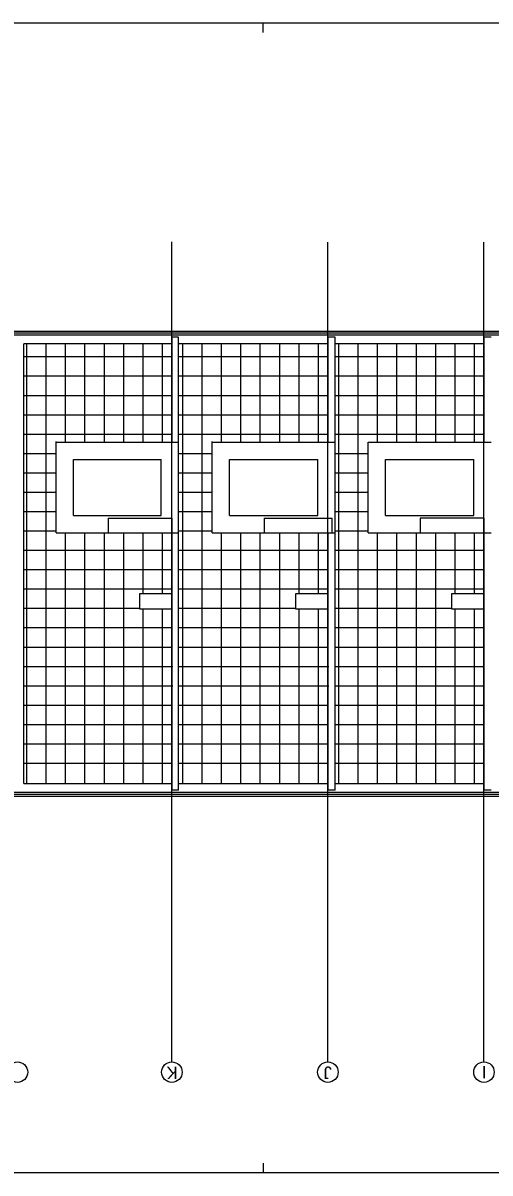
# Model space of a CAD drawing. Extents: x 1278 to 1356, y -443 to -224.
# Drawn here: x 1299.56 to 1311.63, y -253.66 to -223.96 of the extents above; entities that cross this region are included whole.
import ezdxf

# ---------------------------------------------------------------- set-up
doc = ezdxf.new("R2010")
doc.units = 0
for name, color, linetype in [('estrutura-eixos', 7, 'Continuous'), ('Level 2', 7, 'Continuous'), ('Level 21', 7, 'Continuous'), ('Level 60', 7, 'Continuous'), ('Level 62', 7, 'Continuous'), ('Level 70', 7, 'Continuous')]:
    doc.layers.add(name, color=color, linetype=linetype)

msp = doc.modelspace()

# ---------------------------------------------------------------- linework, layer by layer
at = {"layer": 'estrutura-eixos'}
for p, q in [((1303.409, -250.792), (1303.409, -229.609)), ((1307.439, -250.792), (1307.439, -229.62)), ((1311.469, -250.792), (1311.469, -229.62))]:
    msp.add_line(p, q, dxfattribs=at)
at = {"layer": 'Level 2'}
for p, q in [((1303.409, -232.244), (1299.582, -232.244)), ((1307.439, -232.244), (1303.578, -232.244)), ((1311.469, -232.244), (1307.628, -232.244)), ((1299.582, -243.604), (1303.409, -243.604)), ((1303.578, -243.604), (1307.439, -243.604)), ((1307.628, -243.604), (1311.469, -243.604))]:
    msp.add_line(p, q, dxfattribs=at)
at = {"layer": 'Level 21'}
for p, q in [((1299.664, -243.604), (1299.664, -232.244)), ((1300.164, -243.604), (1300.164, -232.244)), ((1300.664, -234.765), (1300.664, -232.244)), ((1301.164, -234.765), (1301.164, -232.244)), ((1301.664, -234.765), (1301.664, -232.244)), ((1302.164, -234.765), (1302.164, -232.244)), ((1302.664, -234.765), (1302.664, -232.244)), ((1303.164, -234.765), (1303.164, -232.244)), ((1303.693, -243.604), (1303.693, -232.244)), ((1304.193, -243.604), (1304.193, -232.244)), ((1304.693, -234.765), (1304.693, -232.244)), ((1305.193, -234.765), (1305.193, -232.244)), ((1305.693, -234.765), (1305.693, -232.244)), ((1306.193, -234.765), (1306.193, -232.244)), ((1306.693, -234.765), (1306.693, -232.244)), ((1307.193, -234.765), (1307.193, -232.244)), ((1307.723, -243.604), (1307.723, -232.244)), ((1308.223, -243.604), (1308.223, -232.244)), ((1308.723, -234.785), (1308.723, -232.244)), ((1309.223, -234.785), (1309.223, -232.244)), ((1309.723, -234.785), (1309.723, -232.244)), ((1310.223, -234.785), (1310.223, -232.244)), ((1310.723, -234.785), (1310.723, -232.244)), ((1311.223, -234.785), (1311.223, -232.244)), ((1303.409, -232.584), (1299.582, -232.584)), ((1307.439, -232.584), (1303.578, -232.584)), ((1311.469, -232.584), (1307.628, -232.584)), ((1303.409, -233.084), (1299.582, -233.084)), ((1307.439, -233.084), (1303.578, -233.084)), ((1311.469, -233.084), (1307.628, -233.084)), ((1303.409, -233.584), (1299.582, -233.584)), ((1307.439, -233.584), (1303.578, -233.584)), ((1311.469, -233.584), (1307.628, -233.584)), ((1303.409, -234.084), (1299.582, -234.084)), ((1307.439, -234.084), (1303.578, -234.084)), ((1311.469, -234.084), (1307.628, -234.084)), ((1303.409, -234.584), (1299.582, -234.584)), ((1307.439, -234.584), (1303.578, -234.584)), ((1311.469, -234.584), (1307.628, -234.584)), ((1300.419, -235.084), (1299.582, -235.084)), ((1304.449, -235.084), (1303.578, -235.084)), ((1308.479, -235.084), (1307.628, -235.084)), ((1300.419, -235.584), (1299.582, -235.584)), ((1304.449, -235.584), (1303.578, -235.584)), ((1308.479, -235.584), (1307.628, -235.584)), ((1300.419, -236.084), (1299.582, -236.084)), ((1304.449, -236.084), (1303.578, -236.084)), ((1308.479, -236.084), (1307.628, -236.084)), ((1300.419, -236.584), (1299.582, -236.584)), ((1304.449, -236.584), (1303.578, -236.584)), ((1308.479, -236.584), (1307.628, -236.584)), ((1300.419, -237.084), (1299.582, -237.084)), ((1300.664, -243.604), (1300.664, -237.126)), ((1301.164, -243.604), (1301.164, -237.126)), ((1301.664, -243.604), (1301.664, -237.126)), ((1302.164, -243.604), (1302.164, -237.126)), ((1302.664, -238.706), (1302.664, -237.126)), ((1303.164, -238.706), (1303.164, -237.126)), ((1304.449, -237.084), (1303.578, -237.084)), ((1304.693, -243.604), (1304.693, -237.127)), ((1305.193, -243.604), (1305.193, -237.127)), ((1305.693, -243.604), (1305.693, -237.127)), ((1306.193, -243.604), (1306.193, -237.127)), ((1306.693, -238.706), (1306.693, -237.127)), ((1307.193, -238.706), (1307.193, -237.127)), ((1308.479, -237.084), (1307.628, -237.084)), ((1308.723, -243.604), (1308.723, -237.126)), ((1309.223, -243.604), (1309.223, -237.126)), ((1309.723, -243.604), (1309.723, -237.126)), ((1310.223, -243.604), (1310.223, -237.126)), ((1310.723, -238.706), (1310.723, -237.126)), ((1311.223, -238.706), (1311.223, -237.126)), ((1303.409, -237.584), (1299.582, -237.584)), ((1307.439, -237.584), (1303.578, -237.584)), ((1311.469, -237.584), (1307.628, -237.584)), ((1303.409, -238.084), (1299.582, -238.084)), ((1307.439, -238.084), (1303.578, -238.084)), ((1311.469, -238.084), (1307.628, -238.084)), ((1303.409, -238.584), (1299.582, -238.584)), ((1307.439, -238.584), (1303.578, -238.584)), ((1311.469, -238.584), (1307.628, -238.584)), ((1302.57, -239.084), (1299.582, -239.084)), ((1306.599, -239.084), (1303.578, -239.084)), ((1310.629, -239.084), (1307.628, -239.084)), ((1302.664, -243.604), (1302.664, -239.086)), ((1303.164, -243.604), (1303.164, -239.086)), ((1306.693, -243.604), (1306.693, -239.086)), ((1307.193, -243.604), (1307.193, -239.086)), ((1310.723, -243.604), (1310.723, -239.086)), ((1311.223, -243.604), (1311.223, -239.086)), ((1303.409, -239.584), (1299.582, -239.584)), ((1307.439, -239.584), (1303.578, -239.584)), ((1311.469, -239.584), (1307.628, -239.584)), ((1303.409, -240.084), (1299.582, -240.084)), ((1307.439, -240.084), (1303.578, -240.084)), ((1311.469, -240.084), (1307.628, -240.084)), ((1303.429, -240.584), (1299.582, -240.584)), ((1307.459, -240.584), (1303.578, -240.584)), ((1311.469, -240.584), (1307.628, -240.584)), ((1303.429, -241.084), (1299.582, -241.084)), ((1307.459, -241.084), (1303.578, -241.084)), ((1311.469, -241.084), (1307.628, -241.084)), ((1303.409, -241.584), (1299.582, -241.584)), ((1307.439, -241.584), (1303.578, -241.584)), ((1311.469, -241.584), (1307.628, -241.584)), ((1303.409, -242.084), (1299.582, -242.084)), ((1307.439, -242.084), (1303.578, -242.084)), ((1311.469, -242.084), (1307.628, -242.084)), ((1303.409, -242.584), (1299.582, -242.584)), ((1307.439, -242.584), (1303.578, -242.584)), ((1311.469, -242.584), (1307.628, -242.584)), ((1303.409, -243.084), (1299.582, -243.084)), ((1307.439, -243.084), (1303.578, -243.084)), ((1311.469, -243.084), (1307.628, -243.084))]:
    msp.add_line(p, q, dxfattribs=at)
at = {"layer": 'Level 60'}
for centre in [(1299.419, -251.055), (1303.409, -251.055), (1307.439, -251.055), (1311.469, -251.055)]:
    msp.add_circle(centre, 0.265, dxfattribs=at)
at = {"layer": 'Level 62'}
for p, q in [((1305.766, -224.209), (1305.766, -223.959)), ((1305.766, -253.409), (1305.766, -253.659))]:
    msp.add_line(p, q, dxfattribs=at)
msp.add_lwpolyline([(1355.966, -223.959), (1355.966, -253.659), (1278.016, -253.659), (1278.016, -223.959)], close=True, dxfattribs=at)
at = {"layer": 'Level 70'}
for p, q in [((1305.766, -224.209), (1305.766, -223.959)), ((1311.543, -231.924), (1299.193, -231.924)), ((1311.593, -231.924), (1311.543, -231.924)), ((1315.493, -231.924), (1311.593, -231.924)), ((1311.593, -231.974), (1299.193, -231.974)), ((1311.593, -232.024), (1299.193, -232.024)), ((1299.582, -243.604), (1299.582, -232.244)), ((1303.578, -232.074), (1303.409, -232.074)), ((1303.409, -232.074), (1303.409, -234.765)), ((1303.578, -243.774), (1303.578, -232.074)), ((1307.628, -232.074), (1307.439, -232.074)), ((1307.439, -232.074), (1307.439, -234.765)), ((1307.628, -243.774), (1307.628, -232.074)), ((1311.469, -232.074), (1311.469, -234.785)), ((1311.658, -232.074), (1311.469, -232.074)), ((1315.643, -231.974), (1311.593, -231.974)), ((1315.643, -232.024), (1311.593, -232.024)), ((1300.419, -237.126), (1300.419, -234.765)), ((1300.419, -234.785), (1303.578, -234.785)), ((1304.449, -237.127), (1304.449, -234.765)), ((1304.449, -234.785), (1307.628, -234.785)), ((1308.479, -234.785), (1311.658, -234.785)), ((1308.479, -237.126), (1308.479, -234.785)), ((1300.869, -236.676), (1300.869, -235.235)), ((1300.869, -235.235), (1303.128, -235.235)), ((1303.128, -236.676), (1303.128, -235.235)), ((1304.899, -236.677), (1304.899, -235.235)), ((1304.899, -235.235), (1307.178, -235.235)), ((1307.178, -236.677), (1307.178, -235.235)), ((1308.929, -236.676), (1308.929, -235.235)), ((1308.929, -235.235), (1311.208, -235.235)), ((1311.208, -236.676), (1311.208, -235.235)), ((1300.869, -236.676), (1303.128, -236.676)), ((1304.899, -236.677), (1307.178, -236.677)), ((1308.929, -236.676), (1311.208, -236.676)), ((1301.763, -236.745), (1303.42, -236.745)), ((1301.763, -236.745), (1301.763, -237.126)), ((1303.42, -237.126), (1303.42, -236.745)), ((1305.793, -236.745), (1307.549, -236.745)), ((1305.793, -236.745), (1305.793, -237.127)), ((1307.549, -237.127), (1307.549, -236.745)), ((1309.823, -236.745), (1309.823, -237.126)), ((1311.478, -236.745), (1309.823, -236.745)), ((1311.478, -237.126), (1311.478, -236.745)), ((1300.419, -237.126), (1303.578, -237.126)), ((1303.409, -237.126), (1303.409, -243.774)), ((1304.449, -237.127), (1307.628, -237.127)), ((1307.439, -237.127), (1307.439, -243.774)), ((1308.479, -237.126), (1311.658, -237.126)), ((1311.469, -237.126), (1311.469, -243.774)), ((1299.193, -243.824), (1318.344, -243.824)), ((1303.578, -243.774), (1303.409, -243.774)), ((1307.628, -243.774), (1307.439, -243.774)), ((1311.658, -243.774), (1311.469, -243.774)), ((1299.193, -243.874), (1318.294, -243.874)), ((1299.193, -243.924), (1318.244, -243.924))]:
    msp.add_line(p, q, dxfattribs=at)
for points in [[(1302.57, -239.086), (1303.409, -239.086), (1303.409, -238.706), (1302.57, -238.706)], [(1306.599, -239.086), (1307.439, -239.086), (1307.439, -238.706), (1306.599, -238.706)], [(1310.629, -239.086), (1311.469, -239.086), (1311.469, -238.706), (1310.629, -238.706)]]:
    msp.add_lwpolyline(points, close=True, dxfattribs=at)

# ---------------------------------------------------------------- texts
at = {"layer": 'Level 60'}
for s, p in [('K', (1303.555, -250.909)), ('J', (1307.538, -250.909)), ('I', (1311.535, -250.897))]:
    msp.add_text(s, height=0.32, rotation=180, dxfattribs=at).set_placement(p)

doc.saveas('drawing.dxf')
